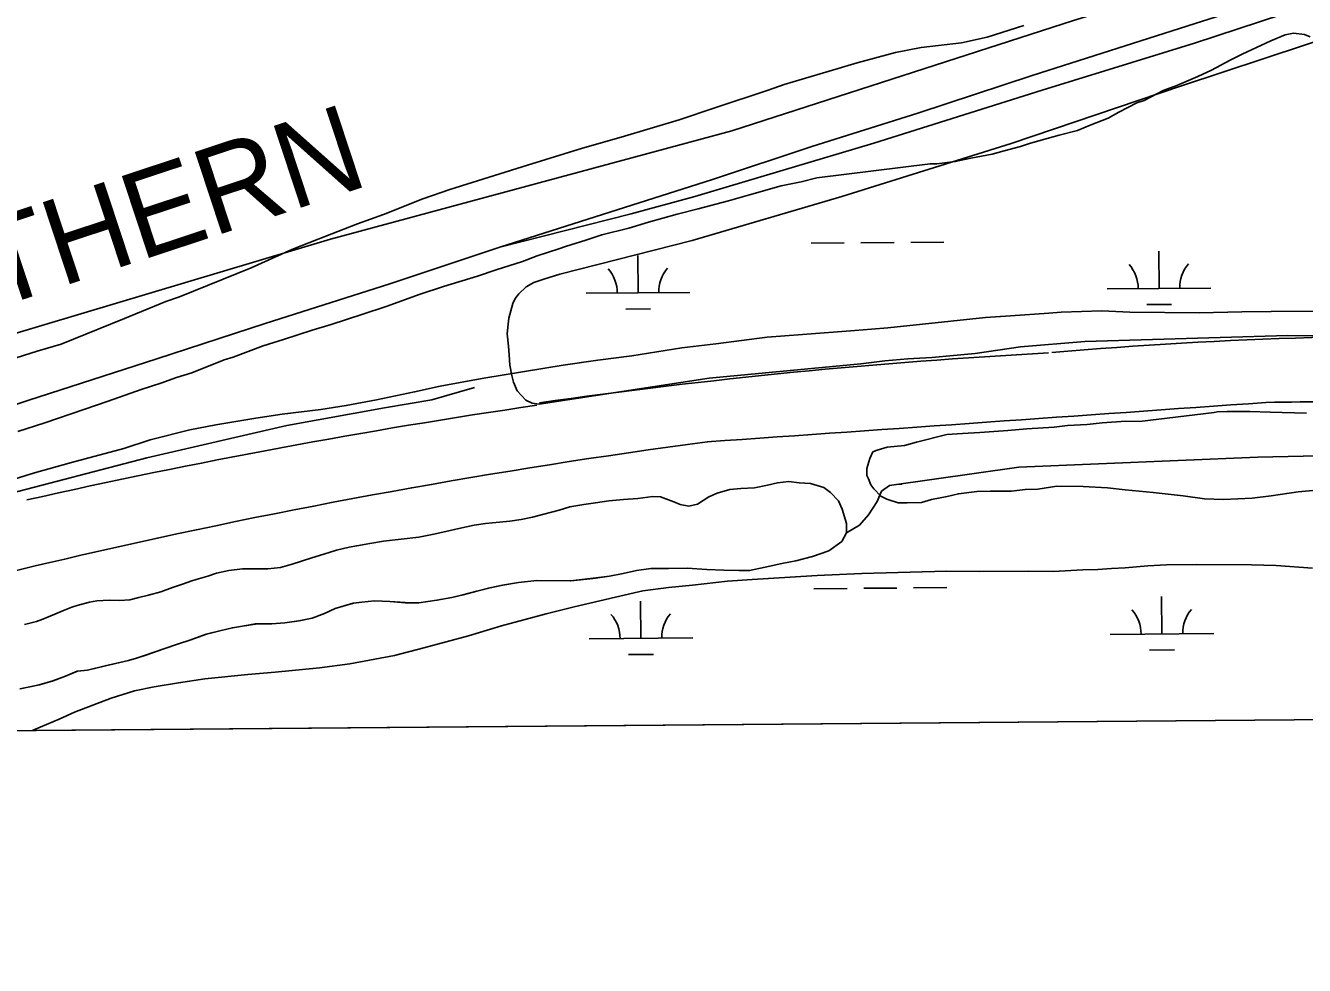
# Model space of a CAD drawing. Extents: x 3567028 to 3605064, y 510945 to 536587.
# Drawn here: x 3598023 to 3599255, y 516349 to 517254 of the extents above; entities that cross this region are included whole.
import ezdxf

# ---------------------------------------------------------------- set-up
doc = ezdxf.new("R2010")
doc.units = 0
for name, color, linetype in [('V-GRID-FRAM', 7, 'Continuous'), ('V-RAIL-IDEN', 7, 'Continuous'), ('V-RAIL-TRAK', 7, 'Continuous'), ('V-ROAD-CNTR', 7, 'Continuous'), ('V-SITE-VEGE', 7, 'Continuous'), ('V-TOPO-SHOR', 7, 'Continuous'), ('V-WETL-SWMP', 7, 'Continuous')]:
    doc.layers.add(name, color=color, linetype=linetype)

msp = doc.modelspace()

# ---------------------------------------------------------------- linework, layer by layer
at = {"layer": 'V-GRID-FRAM'}
msp.add_lwpolyline([(3571081.5, 534531.3), (3602744.1, 534798.4), (3602905.4, 516616.2), (3571226.9, 516349), (3571081.5, 534531.3)], dxfattribs=at)
at = {"layer": 'V-RAIL-TRAK'}
for points in [[(3599408.8, 517320.6), (3599317.3, 517292.3), (3599149.3, 517236.8), (3599002.5, 517191.4), (3598840.4, 517140.4), (3598667.7, 517089.2), (3598606.4, 517072.3), (3598480.1, 517040.3)], [(3597015.7, 516566.5), (3597027.9, 516570.4), (3597151.7, 516610.5), (3597280.9, 516651.7), (3597393.3, 516688.2), (3597489.7, 516719.8), (3597593.9, 516753.5), (3597730.7, 516797.2), (3597824.3, 516827.6), (3597917.4, 516856.7), (3598025.2, 516892.9), (3598149.5, 516933), (3598254, 516966.8), (3598374, 517004.9), (3598480.1, 517040.3), (3598586, 517074.1), (3598684.8, 517105.6), (3598780.6, 517137.4), (3598882.7, 517169.5), (3598992.9, 517205.5), (3599149.8, 517255.8), (3599244, 517285.7)]]:
    msp.add_lwpolyline(points, dxfattribs=at)
at = {"layer": 'V-ROAD-CNTR'}
for centre, radius, start, end in [((3599406.1, 512235.2), 4720.4, 88.7023, 94.7934), ((3599311.3, 511324), 5622.7, 93.0879, 98.1092), ((3599471.5, 510362.2), 6595.6, 98.3338, 102.67404), ((3564933.8, 1000043.4), 484367.4, 273.995055, 274.058852), ((3599339.6, 509774.9), 7117, 88.84995, 90.97964), ((3599550.8, 510318.6), 6592.2, 97.59146, 102.93611), ((3599453.4, 510750.5), 6149.4, 102.95208, 107.31127)]:
    msp.add_arc(centre, radius, start, end, dxfattribs=at)
at = {"layer": 'V-SITE-VEGE'}
for p, q in [((3598984.7, 517253.6), (3598949.6, 517242.5)), ((3598949.6, 517242.5), (3598924.8, 517236.9)), ((3598861, 517227.7), (3598824.2, 517217.7)), ((3598885.8, 517232.7), (3598861, 517227.7)), ((3598924.8, 517236.9), (3598885.8, 517232.7)), ((3598824.2, 517217.7), (3598797.2, 517209.9)), ((3598797.2, 517209.9), (3598754, 517197)), ((3598738.5, 517191.4), (3598687.2, 517174.6)), ((3598754, 517197), (3598738.5, 517191.4)), ((3598687.2, 517174.6), (3598652.7, 517162.9)), ((3598652.7, 517162.9), (3598596.9, 517146.1)), ((3598596.9, 517146.1), (3598559.5, 517135.5)), ((3598559.5, 517135.5), (3598506.5, 517119.3)), ((3598506.5, 517119.3), (3598474.9, 517109.3)), ((3598474.9, 517109.3), (3598431.7, 517095.9)), ((3598431.7, 517095.9), (3598405.8, 517086.9)), ((3598405.8, 517086.9), (3598367.8, 517071.7)), ((3598367.8, 517071.7), (3598343, 517062.8)), ((3598343, 517062.8), (3598305, 517048.2)), ((3598305, 517048.2), (3598279.7, 517038)), ((3598279.7, 517038), (3598240.5, 517020.6)), ((3598240.5, 517020.6), (3598171.3, 516992.5)), ((3598171.3, 516992.5), (3598158.1, 516988)), ((3598158.1, 516988), (3598118.4, 516971.7)), ((3598118.4, 516971.7), (3598093, 516961.5)), ((3598093, 516961.5), (3598057.3, 516946.9)), ((3598057.3, 516946.9), (3598034.3, 516940.2)), ((3598034.3, 516940.2), (3598000.9, 516929.6)), ((3599082.4, 516731.6), (3599104.3, 516733.7)), ((3599104.3, 516733.7), (3599122.1, 516734.7)), ((3599122.1, 516734.7), (3599151.3, 516735)), ((3599151.3, 516735), (3599204.2, 516734.6)), ((3599204.2, 516734.6), (3599227.7, 516733.8)), ((3599227.7, 516733.8), (3599262.7, 516731.2)), ((3598699.4, 516718.8), (3598723, 516720.3)), ((3598723, 516720.3), (3598759.7, 516722.8)), ((3598759.7, 516722.8), (3598785.6, 516724.3)), ((3598785.6, 516724.3), (3598828.7, 516726.3)), ((3598828.7, 516726.3), (3598910.2, 516728.4)), ((3598910.2, 516728.4), (3598942.3, 516728.2)), ((3598942.3, 516728.2), (3598988.8, 516728.4)), ((3598988.8, 516728.4), (3599012.9, 516728.1)), ((3599012.9, 516728.1), (3599041.7, 516729.6)), ((3599041.7, 516729.6), (3599056, 516730.1)), ((3599056, 516730.1), (3599069.2, 516731.1)), ((3599069.2, 516731.1), (3599082.4, 516731.6)), ((3598591.4, 516703.6), (3598617.8, 516709.7)), ((3598617.8, 516709.7), (3598642.6, 516712.9)), ((3598642.6, 516712.9), (3598665.5, 516715)), ((3598665.5, 516715), (3598699.4, 516718.8)), ((3598551.7, 516694.2), (3598591.4, 516703.6)), ((3598481.5, 516675.8), (3598524.7, 516687.5)), ((3598524.7, 516687.5), (3598551.7, 516694.2)), ((3598449.9, 516666.3), (3598481.5, 516675.8)), ((3598406.7, 516654.6), (3598449.9, 516666.3)), ((3598335.4, 516639.2), (3598378.5, 516647.4)), ((3598378.5, 516647.4), (3598406.7, 516654.6)), ((3598263.6, 516631.2), (3598306.1, 516635.4)), ((3598306.1, 516635.4), (3598335.4, 516639.2)), ((3598170.5, 516621.1), (3598195.8, 516624.9)), ((3598195.8, 516624.9), (3598237.1, 516629.1)), ((3598237.1, 516629.1), (3598263.6, 516631.2)), ((3598105.5, 516606.1), (3598127.9, 516613.4)), ((3598127.9, 516613.4), (3598146.9, 516617.2)), ((3598146.9, 516617.2), (3598170.5, 516621.1)), ((3598070.4, 516592.6), (3598105.5, 516606.1)), ((3600244.4, 516593.8), (3598029.9, 516575.1)), ((3598031.2, 516575.7), (3598055.4, 516585.9)), ((3598055.4, 516585.9), (3598070.4, 516592.6)), ((3598029.9, 516575.1), (3598031.2, 516575.7))]:
    msp.add_line(p, q, dxfattribs=at)
for points in [[(3598015.8, 516862.9), (3598041.7, 516871.3), (3598079.2, 516884.2), (3598102.8, 516892), (3598134.4, 516903.2), (3598153.4, 516909.4), (3598168.4, 516915), (3598183.4, 516919.5), (3598214.5, 516931.8), (3598223.1, 516934.6), (3598251.9, 516945.3), (3598271.5, 516951.4), (3598299.1, 516960.4), (3598317.5, 516966), (3598348, 516976), (3598370.5, 516983.3), (3598403.3, 516995.1), (3598425.7, 517002.4), (3598458.5, 517012.4), (3598476.4, 517018.6), (3598501.7, 517026.4), (3598516.1, 517032), (3598536.8, 517038.7), (3598543.2, 517041), (3598562.7, 517047.1), (3598578.3, 517052.2), (3598604.2, 517058.8), (3598623.2, 517064.4), (3598650.8, 517072.2), (3598670.9, 517077.2), (3598700.2, 517085), (3598720.4, 517090.6), (3598750.9, 517099.5), (3598770.4, 517103.3), (3598785.4, 517107.2), (3598894.6, 517120.6), (3598900.9, 517120.6), (3598918.7, 517122.7), (3598933.7, 517126.1), (3598954.4, 517129.9), (3598965.9, 517133.2), (3598981.4, 517137.1), (3598991.2, 517140.5), (3599007.3, 517145), (3599018.8, 517148.3), (3599036.6, 517152.7), (3599048.7, 517157.8), (3599066, 517164.5), (3599076.4, 517170.2), (3599093.7, 517179.2), (3599100.6, 517181.5), (3599119, 517191.1), (3599132.3, 517196.1), (3599152.5, 517204.6), (3599165.7, 517210.8), (3599183.6, 517220.4), (3599195.1, 517226), (3599222.8, 517239), (3599236.6, 517244.6), (3599244.7, 517246.3), (3599255, 517245), (3599260.7, 517242.7)], [(3599265.3, 516978.6), (3599222.9, 516978.4), (3599194.7, 516978), (3599154, 516977.2), (3599086.8, 516977.8), (3599059.8, 516979.2), (3599020.8, 516977.8), (3599008.7, 516976.7), (3598972, 516974.2), (3598947.9, 516972.7), (3598853.6, 516962.6), (3598838.1, 516961.5), (3598822, 516960), (3598771.5, 516956.4), (3598737.6, 516953.8), (3598688.2, 516947.3), (3598655.4, 516943.6), (3598607.1, 516935.9), (3598574.4, 516931.6), (3598541, 516926.8), (3598464.6, 516914.2), (3598422.6, 516906.5), (3598397.9, 516901), (3598361.1, 516893.3), (3598331.8, 516887.8), (3598307.6, 516884), (3598270.3, 516879.7), (3598245, 516875.9), (3598206.5, 516869.3), (3598181.2, 516864.4), (3598143.2, 516854.9), (3598117.9, 516846.5), (3598080.5, 516836.5), (3598067.2, 516833.2), (3598031.6, 516823.2), (3598008, 516815.9)], [(3599096.3, 516872.7), (3599168.1, 516881.2), (3599171, 516881.8), (3599180.7, 516882.3), (3599202.5, 516882.1), (3599222, 516881.4), (3599257.1, 516880.5)], [(3599284.6, 516807.9), (3599249, 516804.8), (3599223.1, 516801), (3599204.7, 516798.9), (3599177.1, 516797.4), (3599158.8, 516798.1), (3599138.1, 516801.1), (3599109.5, 516804.3), (3599082.5, 516806.8), (3599065.3, 516808.6), (3599041.8, 516810), (3599016.5, 516810.2), (3598998.1, 516807.5), (3598986.1, 516807), (3598972.8, 516805.4), (3598952.8, 516805.6), (3598939.5, 516805.1), (3598921.7, 516803), (3598910.8, 516800.2), (3598895.9, 516797.5), (3598886.1, 516794.7), (3598872.3, 516794.2), (3598863.7, 516794.3), (3598852.8, 516797.8), (3598847.1, 516800.7), (3598840.3, 516807.7), (3598837.4, 516811.7), (3598835.2, 516817.5), (3598833.5, 516820.4), (3598833.5, 516827.3), (3598836.5, 516837), (3598839.4, 516843.3), (3598843.4, 516845), (3598853.2, 516847.8), (3598869.9, 516849.3), (3598881.4, 516852.7), (3598910.7, 516859.9), (3598925.7, 516860.9), (3598942.3, 516861.9), (3598969.3, 516864), (3598987.7, 516865.6), (3599014.1, 516867.1), (3599026.8, 516868.7), (3599045.7, 516869.7), (3599060.1, 516871.3), (3599083.1, 516872.8), (3599096.3, 516872.7)]]:
    msp.add_lwpolyline(points, dxfattribs=at)
at = {"layer": 'V-TOPO-SHOR'}
for points in [[(3599918.6, 517551.5), (3599651.5, 517455.4), (3599483.2, 517396.9), (3599374.6, 517363.6), (3599032.6, 517258.4), (3598703.6, 517152.2), (3598316.9, 517047.9), (3597901, 516923.8), (3597461.2, 516806.1), (3597306.9, 516761.6)], [(3598455.7, 516905.4), (3598414.4, 516893.5), (3598368.9, 516885.6), (3598274.8, 516868.7), (3598139.8, 516837.5), (3598002.3, 516801.6), (3597863.3, 516767.2), (3597678.9, 516715.9)], [(3598022, 516677), (3598033.6, 516680), (3598039.6, 516682.2), (3598051.4, 516687.1), (3598059.5, 516690.7), (3598067.6, 516693.7), (3598073.8, 516695.6), (3598084.8, 516698.7), (3598091.6, 516699.8), (3598104, 516700.4), (3598113.5, 516700.2), (3598123.4, 516701), (3598132.3, 516703), (3598141.5, 516705.4), (3598153.4, 516708.7), (3598164.7, 516712.6), (3598174.4, 516715.9), (3598183.3, 516719.2), (3598187.6, 516720.5), (3598198.6, 516723.8), (3598207, 516726.6), (3598218.9, 516729.1), (3598232.1, 516730.8), (3598256.4, 516730.6), (3598268.8, 516732.1), (3598279.9, 516735.1), (3598299, 516741.4), (3598310.3, 516744.7), (3598322.7, 516748.6), (3598334.9, 516751.6), (3598342.1, 516753), (3598354.6, 516755.2), (3598368, 516757.4), (3598384.8, 516759.4), (3598401.8, 516761.1), (3598414.7, 516763.9), (3598427.9, 516766.7), (3598440.6, 516769.4), (3598455.4, 516772.8), (3598466.2, 516774.4), (3598479.5, 516775.6), (3598489.7, 516776.5), (3598500.5, 516778.1), (3598511.3, 516780.4), (3598522.3, 516783.4), (3598537.2, 516787.3), (3598547.4, 516790.3), (3598560.9, 516792.8), (3598572.2, 516794.2), (3598584.9, 516796.2), (3598599, 516797.3), (3598613, 516798.5), (3598627.3, 516800.2), (3598634.9, 516799.9), (3598647.6, 516795.1), (3598653.8, 516792.7), (3598661.9, 516791.2), (3598670.5, 516793.1), (3598681.3, 516799.9), (3598689.4, 516803.7), (3598701.5, 516807), (3598712.3, 516808.2), (3598725.3, 516808.8), (3598737.7, 516811.3), (3598747.6, 516813.5), (3598758.4, 516814.9), (3598768.4, 516813.6), (3598779.2, 516812.9), (3598792, 516808.9), (3598798.5, 516804.1), (3598806.1, 516796.3), (3598809.9, 516788.2), (3598814, 516774.5), (3598813.8, 516765.3)], [(3598813.8, 516765.3), (3598809.5, 516757.1), (3598796.9, 516747.9), (3598781.2, 516742.7), (3598765.1, 516738.5), (3598751.6, 516735.8), (3598735.7, 516732.4), (3598720.6, 516729.1), (3598710.3, 516729.1), (3598695.7, 516729.5), (3598679.5, 516730), (3598660.6, 516731.2)], [(3598569.9, 516721.5), (3598548.3, 516719.3), (3598515.7, 516719.6), (3598498.1, 516717.6), (3598482.8, 516714.9), (3598470.6, 516712.4), (3598457.9, 516709.1), (3598444.5, 516705.7), (3598433.7, 516703), (3598419.4, 516700.5), (3598402.1, 516698), (3598388.9, 516698.1), (3598374, 516699.4), (3598359.2, 516699.9), (3598347, 516698.7), (3598338.9, 516697.6), (3598321.4, 516692.4), (3598311.2, 516687.7), (3598299.3, 516683.1), (3598286.6, 516680.6), (3598272.9, 516678.6), (3598260.2, 516677.7), (3598244.5, 516677.6), (3598234, 516676), (3598222.4, 516674), (3598211.6, 516671.5), (3598197.3, 516667.7), (3598181.4, 516662.2), (3598170.4, 516658.6), (3598156.4, 516653.7), (3598138.9, 516647.6), (3598130, 516644.6), (3598122.4, 516642.4), (3598100, 516637.4), (3598082.8, 516633.3), (3598073.1, 516632.2), (3598061.7, 516627.5), (3598049.6, 516622.9), (3598036.4, 516619), (3598027.2, 516617.1), (3598017.8, 516615.1)], [(3598660.6, 516731.2), (3598642.5, 516731.1), (3598625.5, 516731), (3598611.5, 516729.1), (3598598.8, 516726.3), (3598585.6, 516723.8), (3598569.9, 516721.5)]]:
    msp.add_lwpolyline(points, dxfattribs=at)
at = {"layer": 'V-WETL-SWMP'}
for p, q in [((3598779.8, 517044.2), (3598811.8, 517044.5)), ((3598827.8, 517044.6), (3598859.8, 517044.9)), ((3598875.8, 517045), (3598907.8, 517045.3)), ((3598613.1, 516996.4), (3598612.8, 517032.4)), ((3599115, 517000.6), (3599114.7, 517036.6)), ((3598563.1, 516996), (3598663.1, 516996.8)), ((3599065, 517000.2), (3599165, 517001)), ((3598601.2, 516980.8), (3598625.2, 516981)), ((3599103.1, 516985.1), (3599127.1, 516985.3)), ((3599210.1, 516838.1), (3599456.3, 516843.9)), ((3598979.9, 516828.5), (3599210.1, 516838.1)), ((3598855.2, 516810.9), (3598979.9, 516828.5)), ((3598847.8, 516805.5), (3598855.2, 516810.9)), ((3598864.6, 516812.3), (3598867.1, 516812.3)), ((3598835, 516782.6), (3598843.4, 516795.5)), ((3598843.4, 516795.5), (3598847.8, 516805.5)), ((3598826.6, 516772.7), (3598835, 516782.6)), ((3598813.8, 516765.3), (3598826.6, 516772.7)), ((3598796.9, 516747.9), (3598809.5, 516757.1)), ((3598809.5, 516757.1), (3598813.8, 516765.3)), ((3598781.2, 516742.7), (3598796.9, 516747.9)), ((3598720.6, 516729.1), (3598735.7, 516732.4)), ((3598735.7, 516732.4), (3598751.6, 516735.8)), ((3598751.6, 516735.8), (3598765.1, 516738.5)), ((3598765.1, 516738.5), (3598781.2, 516742.7)), ((3598548.2, 516719.3), (3598569.8, 516721.6)), ((3598569.8, 516721.6), (3598585.6, 516723.8)), ((3598585.6, 516723.8), (3598598.8, 516726.3)), ((3598598.8, 516726.3), (3598611.5, 516729.1)), ((3598611.5, 516729.1), (3598625.5, 516731)), ((3598625.5, 516731), (3598642.5, 516731.1)), ((3598642.5, 516731.1), (3598660.6, 516731.2)), ((3598660.6, 516731.2), (3598679.5, 516730)), ((3598679.5, 516730), (3598695.7, 516729.5)), ((3598695.7, 516729.5), (3598710.3, 516729.1)), ((3598710.3, 516729.1), (3598720.6, 516729.1)), ((3598444.4, 516705.8), (3598457.8, 516709.1)), ((3598457.8, 516709.1), (3598470.5, 516712.4)), ((3598470.5, 516712.4), (3598482.7, 516714.9)), ((3598482.7, 516714.9), (3598498, 516717.7)), ((3598498, 516717.7), (3598515.6, 516719.6)), ((3598515.6, 516719.6), (3598548.2, 516719.3)), ((3598782.6, 516711.6), (3598814.6, 516711.8)), ((3598830.6, 516712), (3598862.5, 516712.2)), ((3598878.5, 516712.4), (3598910.5, 516712.7)), ((3598321.3, 516692.4), (3598338.8, 516697.6)), ((3598338.8, 516697.6), (3598346.9, 516698.7)), ((3598346.9, 516698.7), (3598359.1, 516699.9)), ((3598359.1, 516699.9), (3598373.9, 516699.4)), ((3598373.9, 516699.4), (3598388.8, 516698.2)), ((3598388.8, 516698.2), (3598402, 516698)), ((3598402, 516698), (3598419.3, 516700.5)), ((3598419.3, 516700.5), (3598433.6, 516703)), ((3598433.6, 516703), (3598444.4, 516705.8)), ((3598615.9, 516663.7), (3598615.6, 516699.7)), ((3599117.8, 516668), (3599117.5, 516704)), ((3598286.5, 516680.6), (3598299.2, 516683.1)), ((3598299.2, 516683.1), (3598311.1, 516687.7)), ((3598311.1, 516687.7), (3598321.3, 516692.4)), ((3598197.2, 516667.7), (3598211.5, 516671.5)), ((3598211.5, 516671.5), (3598222.3, 516674)), ((3598222.3, 516674), (3598233.9, 516676)), ((3598233.9, 516676), (3598244.4, 516677.7)), ((3598244.4, 516677.7), (3598260.1, 516677.7)), ((3598260.1, 516677.7), (3598272.8, 516678.6)), ((3598272.8, 516678.6), (3598286.5, 516680.6)), ((3598156.3, 516653.7), (3598170.3, 516658.6)), ((3598170.3, 516658.6), (3598181.3, 516662.2)), ((3598181.3, 516662.2), (3598197.2, 516667.7)), ((3598565.9, 516663.3), (3598665.9, 516664.2)), ((3599067.8, 516667.5), (3599167.8, 516668.4)), ((3598129.9, 516644.6), (3598138.7, 516647.7)), ((3598138.7, 516647.7), (3598156.3, 516653.7)), ((3598604, 516648.2), (3598628, 516648.4)), ((3599105.9, 516652.4), (3599129.9, 516652.6)), ((3598082.7, 516633.3), (3598099.9, 516637.4)), ((3598099.9, 516637.4), (3598122.3, 516642.4)), ((3598122.3, 516642.4), (3598129.9, 516644.6)), ((3598036.3, 516619), (3598049.5, 516622.9)), ((3598049.5, 516622.9), (3598061.6, 516627.5)), ((3598061.6, 516627.5), (3598072.9, 516632.2)), ((3598072.9, 516632.2), (3598082.7, 516633.3)), ((3598017.7, 516615.1), (3598027.1, 516617.1)), ((3598027.1, 516617.1), (3598036.3, 516619)), ((3600286.6, 516594.1), (3597705.7, 516572.4))]:
    msp.add_line(p, q, dxfattribs=at)
msp.add_lwpolyline([(3599454.7, 516952.7), (3599239.2, 516955.2), (3599043.6, 516949.7), (3598981.5, 516944.4), (3598937.9, 516937.9), (3598896.1, 516934.3), (3598873, 516932.9), (3598851, 516930.8), (3598827.8, 516928.2), (3598681.5, 516914.3), (3598517.9, 516889.1), (3598511, 516890.1), (3598505, 516893.2), (3598496.8, 516901.9), (3598493, 516910.3), (3598491.5, 516916.9), (3598489.7, 516926.8), (3598488.9, 516936.7), (3598488.4, 516945.2), (3598487.1, 516956.8), (3598488, 516966.2), (3598488.7, 516972.1), (3598490.7, 516979.1), (3598492.4, 516986), (3598494.8, 516991), (3598498.3, 516995.5), (3598505.2, 517002.2), (3598512.6, 517006.2), (3598522.5, 517009.5), (3598537.8, 517014.3), (3598665.4, 517046.9), (3598809.5, 517089.1), (3598972.5, 517140), (3599136.6, 517195.6), (3599376.5, 517274.8)], dxfattribs=at)
for centre, start, end in [((3598557.9, 516996.4), 359.7115, 41.2552), ((3598668.3, 516997.3), 139.7115, 181.2552), ((3599059.7, 517000.6), 359.7115, 41.2552), ((3599170.2, 517001.6), 139.7115, 181.2552), ((3598560.6, 516663.7), 359.7115, 41.2552), ((3598671.1, 516664.7), 139.7115, 181.2552), ((3599062.5, 516668), 359.7115, 41.2552), ((3599173, 516668.9), 139.7115, 181.2552)]:
    msp.add_arc(centre, 35.2, start, end, dxfattribs=at)

# ---------------------------------------------------------------- texts
at = {"layer": 'V-RAIL-IDEN'}
msp.add_text('SOUTHERN', height=83, rotation=18.2774, dxfattribs=at).set_placement((3597764.4, 516905.3))

doc.saveas('drawing.dxf')
